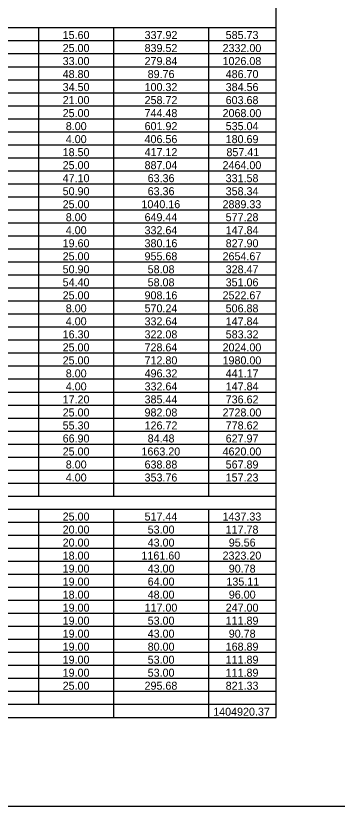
# Model space of a CAD drawing. Extents: x 2261867 to 2275370, y -3124789 to -3122260.
# Drawn here: x 2267663.3 to 2267860.5, y -3124789.4 to -3124303.8 of the extents above; entities that cross this region are included whole.
import ezdxf

# ---------------------------------------------------------------- set-up
doc = ezdxf.new("R2010")
doc.units = 0
doc.layers.add('Default', color=7, linetype='Continuous')
doc.layers.add('DSN_DRFT_Named-Boundary', color=7, linetype='Continuous')

msp = doc.modelspace()

# ---------------------------------------------------------------- linework, layer by layer
at = {"layer": 'Default'}
for p, q in [((2267822.99, -3124734.8), (2267822.99, -3123799.38)), ((2267822.99, -3124734.8), (2267822.99, -3123799.38)), ((2267341.29, -3124311.06), (2267822.99, -3124311.06)), ((2267677.48, -3124598.88), (2267677.48, -3124311.06)), ((2267677.48, -3124598.88), (2267677.48, -3124311.06)), ((2267723.45, -3124311.06), (2267781.81, -3124311.06)), ((2267723.45, -3124598.88), (2267723.45, -3124311.06)), ((2267723.45, -3124598.88), (2267723.45, -3124311.06)), ((2267781.81, -3124598.88), (2267781.81, -3124311.06)), ((2267781.81, -3124598.88), (2267781.81, -3124311.06)), ((2267341.29, -3124319.06), (2267781.81, -3124319.06)), ((2267723.45, -3124319.06), (2267781.81, -3124319.06)), ((2267781.81, -3124319.06), (2267822.99, -3124319.06)), ((2267341.29, -3124327.05), (2267781.81, -3124327.05)), ((2267723.45, -3124327.05), (2267781.81, -3124327.05)), ((2267781.81, -3124327.05), (2267822.99, -3124327.05)), ((2267341.29, -3124335.05), (2267781.81, -3124335.05)), ((2267723.45, -3124335.05), (2267781.81, -3124335.05)), ((2267781.81, -3124335.05), (2267822.99, -3124335.05)), ((2267341.29, -3124343.04), (2267781.81, -3124343.04)), ((2267723.45, -3124343.04), (2267781.81, -3124343.04)), ((2267781.81, -3124343.04), (2267822.99, -3124343.04)), ((2267341.29, -3124351.04), (2267781.81, -3124351.04)), ((2267723.45, -3124351.04), (2267781.81, -3124351.04)), ((2267781.81, -3124351.04), (2267822.99, -3124351.04)), ((2267341.29, -3124359.03), (2267781.81, -3124359.03)), ((2267723.45, -3124359.03), (2267781.81, -3124359.03)), ((2267781.81, -3124359.03), (2267822.99, -3124359.03)), ((2267341.29, -3124367.03), (2267781.81, -3124367.03)), ((2267723.45, -3124367.03), (2267781.81, -3124367.03)), ((2267781.81, -3124367.03), (2267822.99, -3124367.03)), ((2267341.29, -3124375.02), (2267781.81, -3124375.02)), ((2267723.45, -3124375.02), (2267781.81, -3124375.02)), ((2267781.81, -3124375.02), (2267822.99, -3124375.02)), ((2267341.29, -3124383.02), (2267781.81, -3124383.02)), ((2267723.45, -3124383.02), (2267781.81, -3124383.02)), ((2267781.81, -3124383.02), (2267822.99, -3124383.02)), ((2267341.29, -3124391.01), (2267781.81, -3124391.01)), ((2267723.45, -3124391.01), (2267781.81, -3124391.01)), ((2267781.81, -3124391.01), (2267822.99, -3124391.01)), ((2267341.29, -3124399.01), (2267781.81, -3124399.01)), ((2267723.45, -3124399.01), (2267781.81, -3124399.01)), ((2267781.81, -3124399.01), (2267822.99, -3124399.01)), ((2267341.29, -3124407), (2267781.81, -3124407)), ((2267723.45, -3124407), (2267781.81, -3124407)), ((2267781.81, -3124407), (2267822.99, -3124407)), ((2267341.29, -3124415), (2267781.81, -3124415)), ((2267723.45, -3124415), (2267781.81, -3124415)), ((2267781.81, -3124415), (2267822.99, -3124415)), ((2267341.29, -3124422.99), (2267781.81, -3124422.99)), ((2267723.45, -3124422.99), (2267781.81, -3124422.99)), ((2267781.81, -3124422.99), (2267822.99, -3124422.99)), ((2267341.29, -3124430.99), (2267781.81, -3124430.99)), ((2267723.45, -3124430.99), (2267781.81, -3124430.99)), ((2267781.81, -3124430.99), (2267822.99, -3124430.99)), ((2267341.29, -3124438.98), (2267781.81, -3124438.98)), ((2267723.45, -3124438.98), (2267781.81, -3124438.98)), ((2267781.81, -3124438.98), (2267822.99, -3124438.98)), ((2267341.29, -3124446.98), (2267781.81, -3124446.98)), ((2267723.45, -3124446.98), (2267781.81, -3124446.98)), ((2267781.81, -3124446.98), (2267822.99, -3124446.98)), ((2267341.29, -3124454.97), (2267781.81, -3124454.97)), ((2267723.45, -3124454.97), (2267781.81, -3124454.97)), ((2267781.81, -3124454.97), (2267822.99, -3124454.97)), ((2267341.29, -3124462.97), (2267781.81, -3124462.97)), ((2267723.45, -3124462.97), (2267781.81, -3124462.97)), ((2267781.81, -3124462.97), (2267822.99, -3124462.97)), ((2267341.29, -3124470.96), (2267781.81, -3124470.96)), ((2267723.45, -3124470.96), (2267781.81, -3124470.96)), ((2267781.81, -3124470.96), (2267822.99, -3124470.96)), ((2267341.29, -3124478.96), (2267781.81, -3124478.96)), ((2267723.45, -3124478.96), (2267781.81, -3124478.96)), ((2267781.81, -3124478.96), (2267822.99, -3124478.96)), ((2267341.29, -3124486.95), (2267781.81, -3124486.95)), ((2267723.45, -3124486.95), (2267781.81, -3124486.95)), ((2267781.81, -3124486.95), (2267822.99, -3124486.95)), ((2267341.29, -3124494.95), (2267781.81, -3124494.95)), ((2267723.45, -3124494.95), (2267781.81, -3124494.95)), ((2267781.81, -3124494.95), (2267822.99, -3124494.95)), ((2267341.29, -3124502.94), (2267781.81, -3124502.94)), ((2267723.45, -3124502.94), (2267781.81, -3124502.94)), ((2267781.81, -3124502.94), (2267822.99, -3124502.94)), ((2267341.29, -3124510.94), (2267781.81, -3124510.94)), ((2267723.45, -3124510.94), (2267781.81, -3124510.94)), ((2267781.81, -3124510.94), (2267822.99, -3124510.94)), ((2267341.29, -3124518.93), (2267781.81, -3124518.93)), ((2267723.45, -3124518.93), (2267781.81, -3124518.93)), ((2267781.81, -3124518.93), (2267822.99, -3124518.93)), ((2267341.29, -3124526.93), (2267781.81, -3124526.93)), ((2267723.45, -3124526.93), (2267781.81, -3124526.93)), ((2267781.81, -3124526.93), (2267822.99, -3124526.93)), ((2267341.29, -3124534.92), (2267781.81, -3124534.92)), ((2267723.45, -3124534.92), (2267781.81, -3124534.92)), ((2267781.81, -3124534.92), (2267822.99, -3124534.92)), ((2267341.29, -3124542.92), (2267781.81, -3124542.92)), ((2267677.48, -3124542.92), (2267781.81, -3124542.92)), ((2267781.81, -3124542.92), (2267822.99, -3124542.92)), ((2267341.29, -3124550.91), (2267781.81, -3124550.91)), ((2267677.48, -3124550.91), (2267781.81, -3124550.91)), ((2267781.81, -3124550.91), (2267822.99, -3124550.91)), ((2267341.29, -3124558.91), (2267781.81, -3124558.91)), ((2267677.48, -3124558.91), (2267781.81, -3124558.91)), ((2267781.81, -3124558.91), (2267822.99, -3124558.91)), ((2267341.29, -3124566.9), (2267781.81, -3124566.9)), ((2267677.48, -3124566.9), (2267781.81, -3124566.9)), ((2267781.81, -3124566.9), (2267822.99, -3124566.9)), ((2267341.29, -3124574.9), (2267781.81, -3124574.9)), ((2267677.48, -3124574.9), (2267781.81, -3124574.9)), ((2267781.81, -3124574.9), (2267822.99, -3124574.9)), ((2267341.29, -3124582.89), (2267781.81, -3124582.89)), ((2267677.48, -3124582.89), (2267781.81, -3124582.89)), ((2267781.81, -3124582.89), (2267822.99, -3124582.89)), ((2267341.29, -3124590.89), (2267781.81, -3124590.89)), ((2267677.48, -3124590.89), (2267781.81, -3124590.89)), ((2267781.81, -3124590.89), (2267822.99, -3124590.89)), ((2267341.29, -3124598.88), (2267677.48, -3124598.88)), ((2267341.29, -3124598.88), (2267822.99, -3124598.88)), ((2267677.48, -3124598.88), (2267781.81, -3124598.88)), ((2267781.81, -3124598.88), (2267822.99, -3124598.88)), ((2267341.29, -3124606.88), (2267822.99, -3124606.88)), ((2267423.64, -3124606.88), (2267781.81, -3124606.88)), ((2267677.48, -3124726.8), (2267677.48, -3124606.88)), ((2267677.48, -3124726.8), (2267677.48, -3124606.88)), ((2267723.45, -3124734.8), (2267723.45, -3124606.88)), ((2267723.45, -3124734.8), (2267723.45, -3124606.88)), ((2267781.81, -3124734.8), (2267781.81, -3124606.88)), ((2267781.81, -3124726.8), (2267781.81, -3124606.88)), ((2267341.29, -3124614.87), (2267781.81, -3124614.87)), ((2267677.48, -3124614.87), (2267781.81, -3124614.87)), ((2267781.81, -3124614.87), (2267822.99, -3124614.87)), ((2267341.29, -3124622.87), (2267781.81, -3124622.87)), ((2267677.48, -3124622.87), (2267781.81, -3124622.87)), ((2267781.81, -3124622.87), (2267822.99, -3124622.87)), ((2267341.29, -3124630.86), (2267781.81, -3124630.86)), ((2267677.48, -3124630.86), (2267781.81, -3124630.86)), ((2267781.81, -3124630.86), (2267822.99, -3124630.86)), ((2267341.29, -3124638.86), (2267781.81, -3124638.86)), ((2267677.48, -3124638.86), (2267781.81, -3124638.86)), ((2267781.81, -3124638.86), (2267822.99, -3124638.86)), ((2267341.29, -3124646.85), (2267781.81, -3124646.85)), ((2267677.48, -3124646.85), (2267781.81, -3124646.85)), ((2267781.81, -3124646.85), (2267822.99, -3124646.85)), ((2267341.29, -3124654.85), (2267781.81, -3124654.85)), ((2267677.48, -3124654.85), (2267781.81, -3124654.85)), ((2267781.81, -3124654.85), (2267822.99, -3124654.85)), ((2267341.29, -3124662.84), (2267781.81, -3124662.84)), ((2267677.48, -3124662.84), (2267781.81, -3124662.84)), ((2267781.81, -3124662.84), (2267822.99, -3124662.84)), ((2267341.29, -3124670.84), (2267781.81, -3124670.84)), ((2267677.48, -3124670.84), (2267781.81, -3124670.84)), ((2267781.81, -3124670.84), (2267822.99, -3124670.84)), ((2267341.29, -3124678.83), (2267781.81, -3124678.83)), ((2267677.48, -3124678.83), (2267781.81, -3124678.83)), ((2267781.81, -3124678.83), (2267822.99, -3124678.83)), ((2267341.29, -3124686.83), (2267781.81, -3124686.83)), ((2267677.48, -3124686.83), (2267781.81, -3124686.83)), ((2267781.81, -3124686.83), (2267822.99, -3124686.83)), ((2267341.29, -3124694.82), (2267781.81, -3124694.82)), ((2267677.48, -3124694.82), (2267781.81, -3124694.82)), ((2267781.81, -3124694.82), (2267822.99, -3124694.82)), ((2267341.29, -3124702.82), (2267781.81, -3124702.82)), ((2267677.48, -3124702.82), (2267781.81, -3124702.82)), ((2267781.81, -3124702.82), (2267822.99, -3124702.82)), ((2267341.29, -3124710.81), (2267781.81, -3124710.81)), ((2267677.48, -3124710.81), (2267781.81, -3124710.81)), ((2267781.81, -3124710.81), (2267822.99, -3124710.81)), ((2267341.29, -3124718.81), (2267781.81, -3124718.81)), ((2267677.48, -3124718.81), (2267781.81, -3124718.81)), ((2267781.81, -3124718.81), (2267822.99, -3124718.81)), ((2267341.29, -3124726.8), (2267781.81, -3124726.8)), ((2267341.29, -3124726.8), (2267822.99, -3124726.8)), ((2267781.81, -3124726.8), (2267822.99, -3124726.8)), ((2267341.29, -3124734.8), (2267822.99, -3124734.8))]:
    msp.add_line(p, q, dxfattribs=at)
at = {"layer": 'DSN_DRFT_Named-Boundary'}
msp.add_lwpolyline([(2266769.64, -3124789.38), (2268394.64, -3124789.38), (2268394.64, -3123790.32), (2266769.64, -3123790.32)], close=True, dxfattribs=at)

# ---------------------------------------------------------------- texts
at = {"layer": 'Default'}
for s, p in [('15.60', (2267692.03, -3124318.07)), ('337.92', (2267742.3, -3124318.07)), ('585.73', (2267792.05, -3124318.07)), ('25.00', (2267692.03, -3124326.07)), ('839.52', (2267742.3, -3124326.07)), ('2332.00', (2267790.15, -3124326.07)), ('33.00', (2267692.03, -3124334.06)), ('279.84', (2267742.29, -3124334.06)), ('1026.08', (2267790.13, -3124334.06)), ('48.80', (2267692.03, -3124342.06)), ('89.76', (2267744.19, -3124342.06)), ('486.70', (2267792.06, -3124342.06)), ('34.50', (2267692.03, -3124350.05)), ('100.32', (2267742.3, -3124350.05)), ('384.56', (2267792.05, -3124350.05)), ('21.00', (2267692.03, -3124358.05)), ('258.72', (2267742.3, -3124358.05)), ('603.68', (2267792.04, -3124358.05)), ('25.00', (2267692.03, -3124366.04)), ('744.48', (2267742.27, -3124366.04)), ('2068.00', (2267790.15, -3124366.04)), ('8.00', (2267693.94, -3124374.04)), ('601.92', (2267742.3, -3124374.04)), ('535.04', (2267792.06, -3124374.04)), ('4.00', (2267693.94, -3124382.03)), ('406.56', (2267742.28, -3124382.03)), ('180.69', (2267792.04, -3124382.03)), ('18.50', (2267692.03, -3124390.03)), ('417.12', (2267742.3, -3124390.03)), ('857.41', (2267792.52, -3124390.03)), ('25.00', (2267692.03, -3124398.02)), ('887.04', (2267742.29, -3124398.02)), ('2464.00', (2267790.15, -3124398.02)), ('47.10', (2267692.03, -3124406.02)), ('63.36', (2267744.19, -3124406.02)), ('331.58', (2267792.04, -3124406.02)), ('50.90', (2267692.03, -3124414.01)), ('63.36', (2267744.19, -3124414.01)), ('358.34', (2267792.06, -3124414.01)), ('25.00', (2267692.03, -3124422.01)), ('1040.16', (2267740.37, -3124422.01)), ('2889.33', (2267790.14, -3124422.01)), ('8.00', (2267693.94, -3124430)), ('649.44', (2267742.29, -3124430)), ('577.28', (2267792.04, -3124430)), ('4.00', (2267693.94, -3124438)), ('332.64', (2267742.29, -3124438)), ('147.84', (2267792.06, -3124438)), ('19.60', (2267692.03, -3124445.99)), ('380.16', (2267742.28, -3124445.99)), ('827.90', (2267792.06, -3124445.99)), ('25.00', (2267692.03, -3124453.99)), ('955.68', (2267742.27, -3124453.99)), ('2654.67', (2267790.14, -3124453.99)), ('50.90', (2267692.03, -3124461.98)), ('58.08', (2267744.19, -3124461.98)), ('328.47', (2267792.05, -3124461.98)), ('54.40', (2267692.03, -3124469.98)), ('58.08', (2267744.19, -3124469.98)), ('351.06', (2267792.05, -3124469.98)), ('25.00', (2267692.03, -3124477.97)), ('908.16', (2267742.28, -3124477.97)), ('2522.67', (2267790.14, -3124477.97)), ('8.00', (2267693.94, -3124485.97)), ('570.24', (2267742.29, -3124485.97)), ('506.88', (2267792.04, -3124485.97)), ('4.00', (2267693.94, -3124493.96)), ('332.64', (2267742.29, -3124493.96)), ('147.84', (2267792.06, -3124493.96)), ('16.30', (2267692.03, -3124501.96)), ('322.08', (2267742.27, -3124501.96)), ('583.32', (2267792.07, -3124501.96)), ('25.00', (2267692.03, -3124509.95)), ('728.64', (2267742.29, -3124509.95)), ('2024.00', (2267790.15, -3124509.95)), ('25.00', (2267692.03, -3124517.95)), ('712.80', (2267742.29, -3124517.95)), ('1980.00', (2267790.15, -3124517.95)), ('8.00', (2267693.94, -3124525.94)), ('496.32', (2267742.3, -3124525.94)), ('441.17', (2267792.05, -3124525.94)), ('4.00', (2267693.94, -3124533.94)), ('332.64', (2267742.29, -3124533.94)), ('147.84', (2267792.06, -3124533.94)), ('17.20', (2267692.03, -3124541.93)), ('385.44', (2267742.29, -3124541.93)), ('736.62', (2267792.07, -3124541.93)), ('25.00', (2267692.03, -3124549.93)), ('982.08', (2267742.27, -3124549.93)), ('2728.00', (2267790.15, -3124549.93)), ('55.30', (2267692.03, -3124557.92)), ('126.72', (2267742.3, -3124557.92)), ('778.62', (2267792.07, -3124557.92)), ('66.90', (2267692.03, -3124565.92)), ('84.48', (2267744.19, -3124565.92)), ('627.97', (2267792.05, -3124565.92)), ('25.00', (2267692.03, -3124573.91)), ('1663.20', (2267740.38, -3124573.91)), ('4620.00', (2267790.15, -3124573.91)), ('8.00', (2267693.94, -3124581.91)), ('638.88', (2267742.27, -3124581.91)), ('567.89', (2267792.04, -3124581.91)), ('4.00', (2267693.94, -3124589.9)), ('353.76', (2267742.28, -3124589.9)), ('157.23', (2267792.05, -3124589.9)), ('25.00', (2267692.03, -3124613.89)), ('517.44', (2267742.29, -3124613.89)), ('1437.33', (2267790.14, -3124613.89)), ('20.00', (2267692.03, -3124621.88)), ('53.00', (2267744.2, -3124621.88)), ('117.78', (2267792.04, -3124621.88)), ('20.00', (2267692.03, -3124629.88)), ('43.00', (2267744.2, -3124629.88)), ('95.56', (2267793.96, -3124629.88)), ('18.00', (2267692.03, -3124637.87)), ('1161.60', (2267740.38, -3124637.87)), ('2323.20', (2267790.15, -3124637.87)), ('19.00', (2267692.03, -3124645.87)), ('43.00', (2267744.2, -3124645.87)), ('90.78', (2267793.95, -3124645.87)), ('19.00', (2267692.03, -3124653.86)), ('64.00', (2267744.2, -3124653.86)), ('135.11', (2267792.52, -3124653.86)), ('18.00', (2267692.03, -3124661.86)), ('48.00', (2267744.2, -3124661.86)), ('96.00', (2267793.97, -3124661.86)), ('19.00', (2267692.03, -3124669.85)), ('117.00', (2267742.29, -3124669.85)), ('247.00', (2267792.06, -3124669.85)), ('19.00', (2267692.03, -3124677.85)), ('53.00', (2267744.2, -3124677.85)), ('111.89', (2267792.04, -3124677.85)), ('19.00', (2267692.03, -3124685.84)), ('43.00', (2267744.2, -3124685.84)), ('90.78', (2267793.95, -3124685.84)), ('19.00', (2267692.03, -3124693.84)), ('80.00', (2267744.2, -3124693.84)), ('168.89', (2267792.04, -3124693.84)), ('19.00', (2267692.03, -3124701.83)), ('53.00', (2267744.2, -3124701.83)), ('111.89', (2267792.04, -3124701.83)), ('19.00', (2267692.03, -3124709.83)), ('53.00', (2267744.2, -3124709.83)), ('111.89', (2267792.04, -3124709.83)), ('25.00', (2267692.03, -3124717.82)), ('295.68', (2267742.27, -3124717.82)), ('821.33', (2267792.05, -3124717.82)), ('1404920.37', (2267784.4, -3124733.81))]:
    msp.add_text(s, height=4.92, dxfattribs=at).set_placement(p)

doc.saveas('drawing.dxf')
